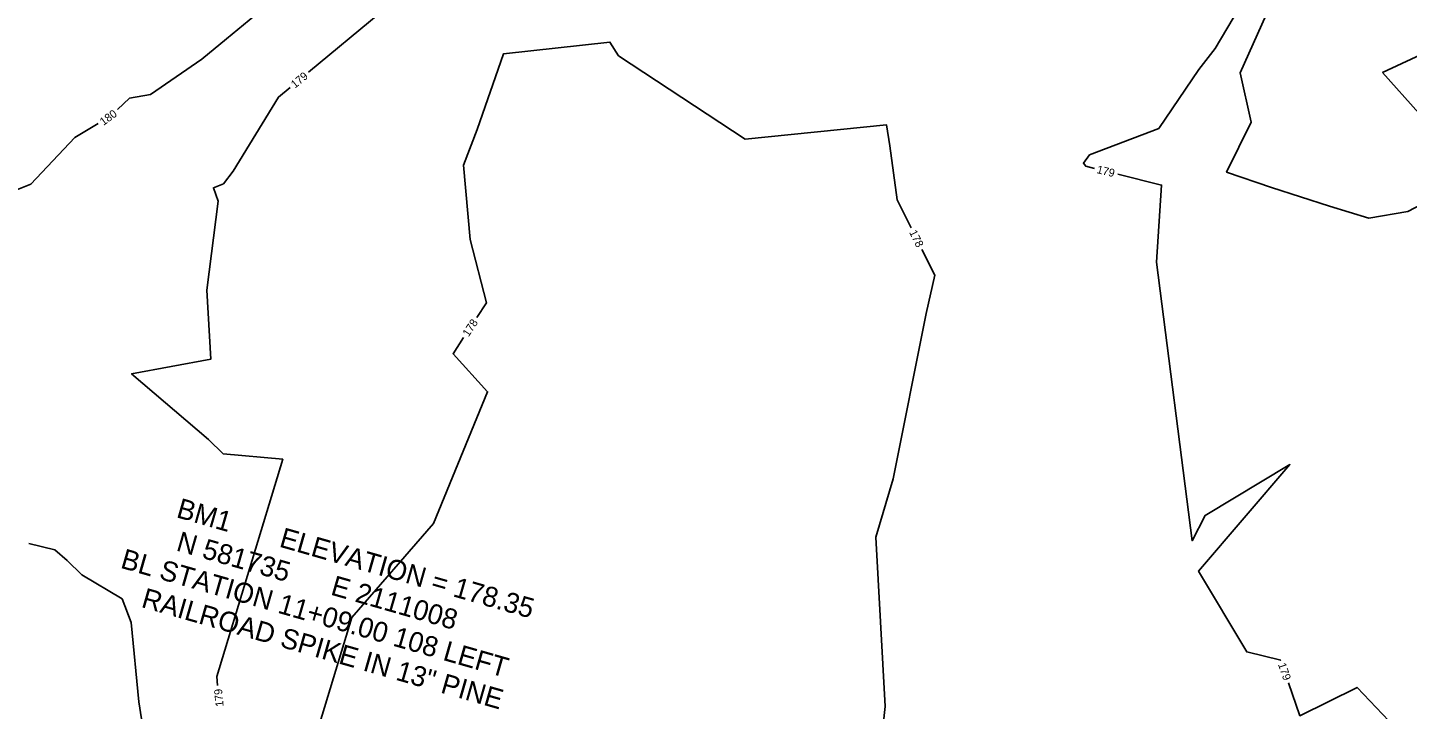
# Model space of a CAD drawing. Extents: x 2086416 to 2115205, y 575507 to 632762.
# Drawn here: x 2110857.5 to 2111202.3, y 581741 to 581911.5 of the extents above; entities that cross this region are included whole.
import ezdxf

# ---------------------------------------------------------------- set-up
doc = ezdxf.new("R2010")
doc.units = 0
for name, color, linetype in [('CTL Supplemental Vertical Text', 7, 'Continuous'), ('DTM Contours Major', 7, 'Continuous'), ('DTM Contours Major Text', 7, 'Continuous'), ('DTM Contours Minor', 7, 'Continuous'), ('DTM Contours Minor Text', 7, 'Continuous')]:
    doc.layers.add(name, color=color, linetype=linetype)

msp = doc.modelspace()

# ---------------------------------------------------------------- linework, layer by layer
at = {"layer": 'DTM Contours Major'}
for points in [[(2110923.69, 581963.96), (2110933.17, 581954.23), (2110923.19, 581930.88), (2110915.68, 581915.67), (2110907.19, 581908.61), (2110901.05, 581903.53), (2110888.2, 581894.74), (2110882.96, 581893.82), (2110879.92, 581890.99)], [(2110875.11, 581887.46), (2110869.25, 581883.98), (2110858.27, 581872.27), (2110849.5, 581868.78), (2110838.87, 581863.56), (2110837.24, 581863.88), (2110827.93, 581865.43), (2110806.43, 581868), (2110795.23, 581869.03), (2110791.72, 581866.92), (2110792.22, 581863.37), (2110794.35, 581859.78)], [(2110857.81, 581782.51), (2110864.26, 581780.86), (2110867.35, 581778.23), (2110871.08, 581774.64), (2110881.14, 581768.63), (2110883.33, 581762.7), (2110885.27, 581742.86), (2110889.69, 581714.76), (2110888.79, 581707.91), (2110885.2, 581704.69), (2110879.38, 581703.43)]]:
    msp.add_lwpolyline(points, dxfattribs=at)
at = {"layer": 'DTM Contours Minor'}
for points in [[(2110977.96, 582064.43), (2110977.78, 582029.54), (2110971.46, 582021.26), (2110946.55, 582002.01), (2110943.51, 581982.57), (2110965.2, 581960.31), (2110947.92, 581919.91), (2110945.57, 581915.16), (2110927.73, 581900.3)], [(2111170.59, 581922.5), (2111171.12, 581923.7), (2111191.31, 581923.5), (2111192.75, 581915.59), (2111194.66, 581925.18), (2111193.07, 581929.37), (2111178.43, 581934.75), (2111171.1, 581931.08), (2111146.2, 581947.93), (2111166.75, 581927.2), (2111154.26, 581906.23), (2111150.19, 581900.99), (2111140.18, 581886.2), (2111122.91, 581879.61), (2111121.36, 581877.57), (2111121.94, 581876.79), (2111124.1, 581876.26)], [(2111268.74, 581824.66), (2111270.41, 581828.31), (2111271.33, 581850.23), (2111267.38, 581862.23), (2111254.62, 581863.65), (2111243.58, 581868.14), (2111220.45, 581874.8), (2111220.28, 581874.83), (2111202.41, 581865.47), (2111192.71, 581863.81), (2111182.9, 581866.81), (2111168.35, 581871.46), (2111157.17, 581875.34), (2111163.3, 581887.8), (2111160.57, 581900.16), (2111168.13, 581917.03)], [(2110969.77, 581838.97), (2110972.19, 581842.63), (2110968.09, 581858.51), (2110966.39, 581877.1), (2110969.83, 581885.98), (2110976.45, 581904.9), (2111003.04, 581907.83), (2111005.16, 581904.43), (2111036.86, 581883.56), (2111072.17, 581887.14), (2111073.02, 581881.87), (2111074.85, 581868.37), (2111078.33, 581861.37)], [(2111246.81, 581901.29), (2111245.27, 581905.18), (2111230.04, 581910.54), (2111218.84, 581910.81), (2111196.15, 581900.2), (2111205.17, 581890.04)], [(2110923.11, 581896.47), (2110920.2, 581894.07), (2110908.89, 581875.53), (2110906.44, 581872.43), (2110903.92, 581871.43), (2110905.1, 581868.04), (2110902.25, 581845.78), (2110903.28, 581828.56), (2110883.48, 581824.9), (2110902.68, 581808.48), (2110906.39, 581804.92), (2110921.27, 581803.56), (2110904.76, 581749.19), (2110904.98, 581746.94)], [(2111129.93, 581874.82), (2111140.92, 581872.1), (2111139.65, 581852.84), (2111148.52, 581783.18), (2111151.82, 581789.49), (2111172.99, 581802.2), (2111150.14, 581775.57), (2111162.21, 581755.37), (2111170.68, 581753.28), (2111170.68, 581753.28)], [(2111081, 581856), (2111084.22, 581849.53), (2111082.1, 581839.99), (2111073.86, 581798.62), (2111069.52, 581784.09), (2111071.86, 581741.69), (2111069.35, 581718.81), (2111065.8, 581715.4), (2111065.15, 581711.2), (2111071.08, 581703.02), (2111084.39, 581695.44), (2111094.41, 581671.9)], [(2110961.28, 581697.94), (2110941.02, 581712.61), (2110935.39, 581696.68), (2110926.5, 581703.26), (2110928.29, 581717.02), (2110927.56, 581721.64), (2110927.09, 581726.43), (2110938.5, 581764.02), (2110958.94, 581787.46), (2110972.43, 581820.41), (2110963.81, 581829.93), (2110966.47, 581833.96)], [(2111172.65, 581747.61), (2111175.49, 581739.43), (2111189.76, 581746.49), (2111199.26, 581736.52), (2111204.94, 581734.72), (2111216.79, 581733.74), (2111237.11, 581749.36), (2111239.88, 581756.72), (2111243.14, 581765.77), (2111244.32, 581774.22), (2111268.57, 581772.28), (2111270.42, 581774.52), (2111272.15, 581778.4), (2111272.02, 581797.41), (2111269.39, 581820.52), (2111268.74, 581824.66)]]:
    msp.add_lwpolyline(points, dxfattribs=at)

# ---------------------------------------------------------------- texts
at = {"layer": 'CTL Supplemental Vertical Text'}
for s, p in [('BM1       ELEVATION = 178.35', (2110894.43, 581789.09)), ('N 581735      E 2111008', (2110894.39, 581780.78)), ('BL STATION 11+09.00 108 LEFT', (2110880.46, 581776.45)), ('RAILROAD SPIKE IN 13" PINE', (2110885.66, 581766.64))]:
    msp.add_text(s, height=5, rotation=344.0427, dxfattribs=at).set_placement(p)
at = {"layer": 'DTM Contours Major Text'}
msp.add_text('180', height=2, rotation=36.2769, dxfattribs=at).set_placement((2110876.44, 581886.85))
at = {"layer": 'DTM Contours Minor Text'}
for s, rotation, p in [('179', 39.6283, (2110924.31, 581896.16)), ('179', 346.0929, (2111124.57, 581875.11)), ('178', 296.4251, (2111077.76, 581860.28)), ('178', 56.559, (2110967.7, 581834.01)), ('179', 289.177, (2111169.97, 581752.27)), ('179', 95.5873, (2110906.49, 581741.78))]:
    msp.add_text(s, height=2, rotation=rotation, dxfattribs=at).set_placement(p)

doc.saveas('drawing.dxf')
